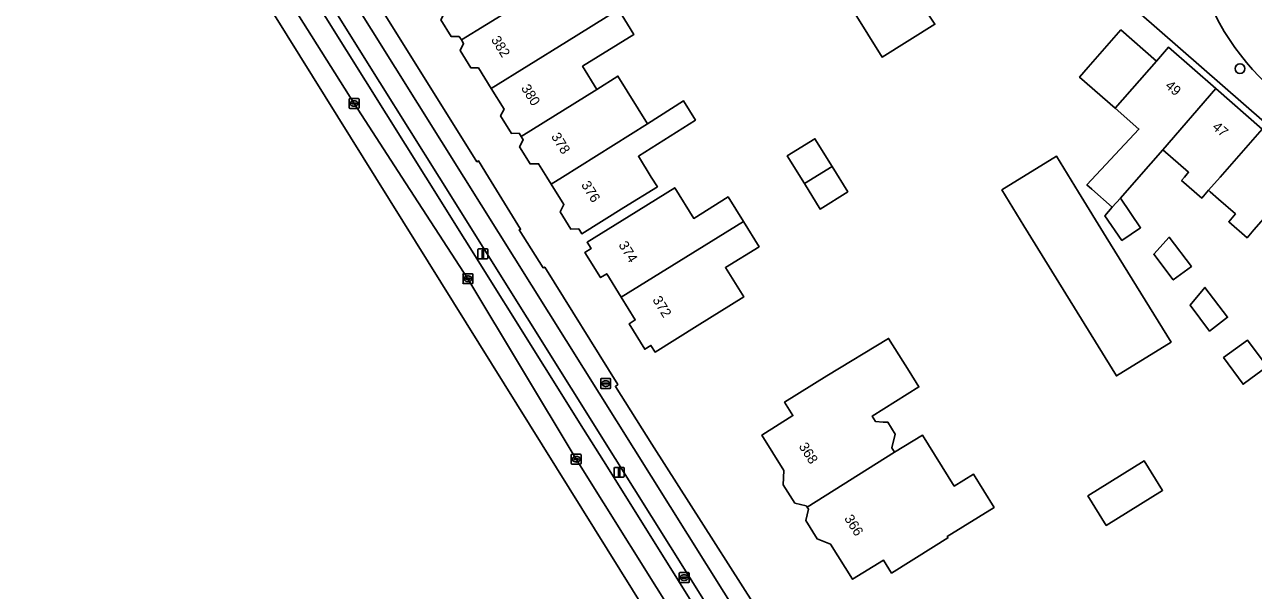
# Model space of a CAD drawing. Extents: x 160023 to 161302, y 384750 to 385707.
# Drawn here: x 160026 to 160150, y 385208.4 to 385265.4 of the extents above; entities that cross this region are included whole.
import ezdxf

# ---------------------------------------------------------------- set-up
doc = ezdxf.new("R2010")
doc.units = 0
for name, color, linetype in [('IMGEO_Berm_open', 7, 'Continuous'), ('IMGEO_Boom', 7, 'Continuous'), ('IMGEO_Brandkraan', 7, 'Continuous'), ('IMGEO_Erf', 7, 'Continuous'), ('IMGEO_Fietspad_gesloten', 7, 'Continuous'), ('IMGEO_Kolk', 7, 'Continuous'), ('IMGEO_Lichtmast', 7, 'Continuous'), ('IMGEO_Pand', 7, 'Continuous'), ('IMGEO_Pand_nummerreeks', 7, 'Continuous'), ('IMGEO_Parkeervlak_open', 7, 'Continuous'), ('IMGEO_Rijbaan_lokaal_gesloten', 7, 'Continuous'), ('IMGEO_Rijbaan_regionaal_gesloten', 7, 'Continuous'), ('IMGEO_Rioolput', 7, 'Continuous'), ('IMGEO_Voetpad_open', 7, 'Continuous')]:
    doc.layers.add(name, color=color, linetype=linetype)

msp = doc.modelspace()

# ---------------------------------------------------------------- linework, layer by layer
at = {"layer": 'IMGEO_Berm_open'}
for points in [[(160150.57, 385117.95), (160124.15, 385160.16), (160085.58, 385221.63), (160067.83, 385250), (160061.87, 385259.54), (160032.54, 385306.42)], [(160040.41, 385291.63), (160066.49, 385250), (160082.4, 385224.6), (160084.81, 385220.76), (160099.16, 385197.85), (160101.17, 385194.65), (160111.68, 385177.87), (160112.14, 385178.14), (160114.11, 385174.95), (160113.69, 385174.67), (160123.81, 385158.57), (160123.88, 385157.79), (160123.49, 385155.85)]]:
    msp.add_lwpolyline(points, dxfattribs=at)
at = {"layer": 'IMGEO_Boom'}
msp.add_circle((160148.61, 385260.93), 0.489, dxfattribs=at)
at = {"layer": 'IMGEO_Brandkraan'}
for p, q in [((160084.14, 385228.76), (160084.14, 385229.62)), ((160084.22, 385229.69), (160085.07, 385229.69)), ((160084.4, 385229.18), (160084.4, 385229.2)), ((160084.44, 385229.23), (160084.84, 385229.23)), ((160084.84, 385229.15), (160084.44, 385229.15)), ((160084.63, 385229.47), (160084.66, 385229.47)), ((160084.89, 385229.2), (160084.89, 385229.18)), ((160085.14, 385229.62), (160085.14, 385228.76)), ((160085.07, 385228.69), (160084.22, 385228.69)), ((160084.65, 385228.91), (160084.63, 385228.91))]:
    msp.add_line(p, q, dxfattribs=at)
for points in [[(160084.14, 385228.76), (160084.14, 385229.62)], [(160084.22, 385229.69), (160085.07, 385229.69)], [(160085.14, 385229.62), (160085.14, 385228.76)], [(160085.07, 385228.69), (160084.22, 385228.69)]]:
    msp.add_lwpolyline(points, dxfattribs=at)
for centre, radius, start, end in [((160084.22, 385229.62), 0.0765, 91.552, 178.448), ((160084.22, 385229.62), 0.0765, 91.552, 178.448), ((160084.44, 385229.19), 0.0403, 85.8775, 175.7526), ((160084.44, 385229.18), 0.0366, 178.938, 274.7102), ((160084.85, 385229.2), 0.0386, 1.7309, 96.639), ((160084.84, 385229.19), 0.043, 264.8664, 352.4533), ((160085.07, 385229.62), 0.0765, 1.552, 88.448), ((160085.07, 385229.62), 0.0765, 1.552, 88.448), ((160084.22, 385228.77), 0.0765, 181.552, 268.448), ((160084.22, 385228.77), 0.0765, 181.552, 268.448), ((160085.07, 385228.77), 0.0765, 271.552, 358.448), ((160085.07, 385228.77), 0.0765, 271.552, 358.448)]:
    msp.add_arc(centre, radius, start, end, dxfattribs=at)
for centre, major_axis, ratio, start_param, end_param in [((160084.63, 385229.19), (-0.387, 0.002), 0.722429, 4.712389, 7.853982), ((160084.65, 385229.19), (-0.39, 0.002), 0.717154, 1.570796, 4.712389)]:
    msp.add_ellipse(centre, major_axis=major_axis, ratio=ratio, start_param=start_param, end_param=end_param, dxfattribs=at)
at = {"layer": 'IMGEO_Erf'}
for points in [[(160152.01, 385315.35), (160133.21, 385328.22), (160132.92, 385328.42), (160128.79, 385322.11), (160120.91, 385304.2), (160118.51, 385298.76), (160117.26, 385295.93), (160116.02, 385293.09), (160114.77, 385290.25), (160113.7, 385287.74), (160114.62, 385287.35), (160116.68, 385286.45), (160114.75, 385282.01), (160113.13, 385278.26), (160115.09, 385275.32), (160112.42, 385273.54), (160114.46, 385270.47), (160117.84, 385265.4), (160112.51, 385262.09), (160109.63, 385266.73), (160106.44, 385271.87)], [(160050.76, 385284.96), (160071.65, 385251.54), (160071.81, 385251.64), (160072.82, 385250), (160076.05, 385244.74), (160075.93, 385244.69), (160078.33, 385240.86), (160078.49, 385240.93), (160085.88, 385229.1), (160085.62, 385228.91), (160089.29, 385223.09), (160103.46, 385200.92)], [(160157.45, 385250), (160136.27, 385268.49)], [(160085.93, 385266.87), (160087.48, 385264.38), (160082.31, 385261.17), (160083.75, 385258.84), (160085.88, 385260.17), (160088.85, 385255.37), (160092.49, 385257.68), (160093.69, 385255.75), (160087.94, 385252.09), (160089.24, 385250), (160089.85, 385249.02), (160086.48, 385246.92), (160082.23, 385244.29), (160081.93, 385244.77), (160081.14, 385244.75), (160080.05, 385246.51), (160080.43, 385247.22), (160079.14, 385249.28), (160078.7, 385250), (160077.87, 385251.34), (160077.02, 385251.32), (160075.95, 385253.05), (160076.33, 385253.75), (160076.11, 385254.09), (160075.9, 385254.42), (160075.14, 385254.4), (160074.04, 385256.17), (160074.4, 385256.85), (160073.1, 385258.94), (160071.81, 385261.02), (160071.04, 385261), (160069.95, 385262.77), (160070.31, 385263.46), (160070.09, 385263.82), (160069.86, 385264.18), (160069.06, 385264.15), (160068.01, 385265.85)], [(160150.02, 385244.67), (160149.33, 385243.88), (160147.48, 385245.5), (160148.16, 385246.29), (160146.44, 385247.79), (160145.61, 385248.52), (160145.44, 385248.67), (160144.76, 385247.89), (160142.72, 385249.67), (160143.01, 385250), (160143.43, 385250.48), (160140.82, 385252.76), (160138.4, 385250), (160136.55, 385247.88), (160138.59, 385244.9), (160136.7, 385243.61), (160134.99, 385246.1), (160135.74, 385246.96), (160133.67, 385248.78), (160133.18, 385249.21), (160138.42, 385254.83), (160136.02, 385256.93), (160132.44, 385260.06), (160133.31, 385261.06), (160136.6, 385264.82), (160140.18, 385261.69), (160141.41, 385263.09), (160146.19, 385258.91), (160150.84, 385254.84)]]:
    msp.add_lwpolyline(points, dxfattribs=at)
for points in [[(160109.06, 385248.52), (160106.26, 385246.78), (160104.68, 385249.34), (160102.95, 385252.13), (160105.75, 385253.87), (160107.48, 385251.07)], [(160130.12, 385252.09), (160132.34, 385248.49), (160135.13, 385243.96), (160141.66, 385233.37), (160136.16, 385229.97), (160126.83, 385245.1), (160124.61, 385248.7)], [(160100.11, 385242.98), (160096.72, 385240.88), (160098.56, 385237.92), (160093.87, 385235.01), (160089.62, 385232.37), (160089.2, 385233.04), (160088.58, 385232.65), (160087, 385235.21), (160087.63, 385235.6), (160086.2, 385237.9), (160084.74, 385240.26), (160084.12, 385239.88), (160082.55, 385242.41), (160083.17, 385242.8), (160082.77, 385243.44), (160087.02, 385246.07), (160091.61, 385248.92), (160093.52, 385245.84), (160096.99, 385248), (160098.53, 385245.53)], [(160141.48, 385243.94), (160143.71, 385241), (160141.89, 385239.63), (160139.92, 385242.22)], [(160145.08, 385238.88), (160147.36, 385235.87), (160145.55, 385234.49), (160143.58, 385237.09)], [(160121.73, 385220.08), (160123.82, 385216.71), (160119.09, 385213.77), (160119.16, 385213.64), (160117.71, 385212.74), (160113.47, 385210.1), (160112.66, 385211.4), (160109.55, 385209.47), (160107.33, 385213), (160105.96, 385213.55), (160104.82, 385215.38), (160105.08, 385216.53), (160104.96, 385216.73), (160104.86, 385216.89), (160103.73, 385217.15), (160102.55, 385218.98), (160102.62, 385220.43), (160100.39, 385224), (160103.53, 385225.96), (160102.68, 385227.33), (160106.93, 385229.97), (160113.18, 385233.75), (160115.24, 385230.44), (160116.23, 385228.86), (160111.52, 385225.92), (160111.86, 385225.37), (160112.62, 385225.32), (160113.1, 385225.3), (160113.85, 385224.09), (160113.5, 385222.73), (160113.78, 385222.29), (160116.59, 385224.01), (160119.79, 385218.87)], [(160149.37, 385233.58), (160151.34, 385230.9), (160149.07, 385229.23), (160148.93, 385229.13), (160146.96, 385231.81)], [(160138.95, 385221.42), (160140.81, 385218.43), (160135.13, 385214.9), (160133.27, 385217.88)]]:
    msp.add_lwpolyline(points, close=True, dxfattribs=at)
at = {"layer": 'IMGEO_Fietspad_gesloten'}
msp.add_lwpolyline([(160026.03, 385317.31), (160026.04, 385317.29), (160028.01, 385313.74), (160028.32, 385313.16), (160030.44, 385309.78), (160032.54, 385306.42), (160061.87, 385259.54), (160067.83, 385250), (160085.58, 385221.63), (160124.15, 385160.16), (160150.57, 385117.95), (160168.15, 385089.8), (160170.06, 385090.86), (160169.92, 385091.09), (160127.68, 385158.49), (160123.78, 385164.74), (160087.49, 385222.64), (160070.35, 385250), (160030.7, 385313.28), (160030.2, 385314.14), (160029.34, 385315.62), (160028.12, 385317.71), (160027.3, 385319.1), (160027.28, 385319.14)], close=True, dxfattribs=at)
at = {"layer": 'IMGEO_Kolk'}
for p, q in [((160058.76, 385256.99), (160058.76, 385257.84)), ((160058.84, 385257.91), (160059.69, 385257.91)), ((160059.25, 385257.69), (160059.28, 385257.69)), ((160059.77, 385257.84), (160059.77, 385256.99)), ((160059.69, 385256.91), (160058.84, 385256.91)), ((160059.02, 385257.41), (160059.02, 385257.42)), ((160059.46, 385257.37), (160059.06, 385257.37)), ((160059.07, 385257.46), (160059.46, 385257.46)), ((160059.27, 385257.13), (160059.25, 385257.13)), ((160059.51, 385257.42), (160059.51, 385257.41)), ((160070.25, 385239.33), (160070.25, 385240.19)), ((160070.32, 385240.26), (160071.18, 385240.26)), ((160071.25, 385240.19), (160071.25, 385239.33)), ((160071.18, 385239.26), (160070.32, 385239.26)), ((160070.51, 385239.75), (160070.51, 385239.77)), ((160070.55, 385239.8), (160070.95, 385239.8)), ((160070.94, 385239.72), (160070.55, 385239.72)), ((160070.76, 385239.48), (160070.73, 385239.48)), ((160070.74, 385240.04), (160070.76, 385240.04)), ((160070.99, 385239.77), (160070.99, 385239.75)), ((160081.17, 385221.15), (160081.17, 385222)), ((160081.24, 385222.07), (160082.09, 385222.07)), ((160081.42, 385221.57), (160081.42, 385221.58)), ((160081.47, 385221.62), (160081.87, 385221.62)), ((160081.65, 385221.85), (160081.68, 385221.85)), ((160081.91, 385221.58), (160081.91, 385221.57)), ((160082.17, 385222), (160082.17, 385221.15)), ((160082.09, 385221.07), (160081.24, 385221.07)), ((160081.86, 385221.53), (160081.46, 385221.53)), ((160081.68, 385221.29), (160081.65, 385221.29))]:
    msp.add_line(p, q, dxfattribs=at)
for points in [[(160058.76, 385256.99), (160058.76, 385257.84)], [(160058.84, 385257.91), (160059.69, 385257.91)], [(160059.77, 385257.84), (160059.77, 385256.99)], [(160059.69, 385256.91), (160058.84, 385256.91)], [(160070.25, 385239.33), (160070.25, 385240.19)], [(160070.32, 385240.26), (160071.18, 385240.26)], [(160071.25, 385240.19), (160071.25, 385239.33)], [(160071.18, 385239.26), (160070.32, 385239.26)], [(160081.17, 385221.15), (160081.17, 385222)], [(160081.24, 385222.07), (160082.09, 385222.07)], [(160082.17, 385222), (160082.17, 385221.15)], [(160082.09, 385221.07), (160081.24, 385221.07)]]:
    msp.add_lwpolyline(points, dxfattribs=at)
for centre, radius, start, end in [((160058.84, 385257.84), 0.0765, 91.552, 178.448), ((160058.84, 385257.84), 0.0765, 91.552, 178.448), ((160059.69, 385257.84), 0.0765, 1.552, 88.448), ((160059.69, 385257.84), 0.0765, 1.552, 88.448), ((160058.84, 385256.99), 0.0765, 181.552, 268.448), ((160058.84, 385256.99), 0.0765, 181.552, 268.448), ((160059.06, 385257.42), 0.0403, 85.8775, 175.7526), ((160059.06, 385257.41), 0.0366, 178.938, 274.7102), ((160059.47, 385257.42), 0.0386, 1.7309, 96.639), ((160059.46, 385257.41), 0.043, 264.8664, 352.4533), ((160059.69, 385256.99), 0.0765, 271.552, 358.448), ((160059.69, 385256.99), 0.0765, 271.552, 358.448), ((160070.32, 385240.19), 0.0765, 91.552, 178.448), ((160070.32, 385240.19), 0.0765, 91.552, 178.448), ((160071.17, 385240.19), 0.0765, 1.552, 88.448), ((160071.17, 385240.19), 0.0765, 1.552, 88.448), ((160070.32, 385239.34), 0.0765, 181.552, 268.448), ((160070.32, 385239.34), 0.0765, 181.552, 268.448), ((160070.55, 385239.76), 0.0403, 85.8775, 175.7526), ((160070.54, 385239.75), 0.0366, 178.938, 274.7102), ((160070.95, 385239.76), 0.043, 264.8664, 352.4533), ((160070.95, 385239.77), 0.0386, 1.7309, 96.639), ((160071.17, 385239.34), 0.0765, 271.552, 358.448), ((160071.17, 385239.34), 0.0765, 271.552, 358.448), ((160081.24, 385222), 0.0765, 91.552, 178.448), ((160081.24, 385222), 0.0765, 91.552, 178.448), ((160081.47, 385221.58), 0.0403, 85.8775, 175.7526), ((160081.46, 385221.57), 0.0366, 178.938, 274.7102), ((160081.87, 385221.57), 0.043, 264.8664, 352.4533), ((160081.87, 385221.58), 0.0386, 1.7309, 96.639), ((160082.09, 385222), 0.0765, 1.552, 88.448), ((160082.09, 385222), 0.0765, 1.552, 88.448), ((160081.24, 385221.15), 0.0765, 181.552, 268.448), ((160081.24, 385221.15), 0.0765, 181.552, 268.448), ((160082.09, 385221.15), 0.0765, 271.552, 358.448), ((160082.09, 385221.15), 0.0765, 271.552, 358.448)]:
    msp.add_arc(centre, radius, start, end, dxfattribs=at)
for centre, major_axis, ratio, start_param, end_param in [((160059.25, 385257.41), (-0.387, 0.002), 0.722429, 4.712389, 7.853982), ((160059.28, 385257.41), (-0.39, 0.002), 0.717154, 1.570796, 4.712389), ((160070.74, 385239.76), (-0.387, 0.002), 0.722429, 4.712389, 7.853982), ((160070.76, 385239.76), (-0.39, 0.002), 0.717154, 1.570796, 4.712389), ((160081.65, 385221.57), (-0.387, 0.002), 0.722429, 4.712389, 7.853982), ((160081.68, 385221.57), (-0.39, 0.002), 0.717154, 1.570796, 4.712389)]:
    msp.add_ellipse(centre, major_axis=major_axis, ratio=ratio, start_param=start_param, end_param=end_param, dxfattribs=at)
at = {"layer": 'IMGEO_Lichtmast'}
for p, q in [((160071.76, 385241.86), (160071.76, 385242.66)), ((160071.76, 385242.66), (160071.76, 385241.86)), ((160071.86, 385242.76), (160072.65, 385242.76)), ((160072.65, 385242.76), (160071.86, 385242.76)), ((160072.75, 385242.66), (160072.75, 385241.86)), ((160072.75, 385241.86), (160072.75, 385242.66)), ((160072.65, 385241.76), (160071.86, 385241.76)), ((160071.86, 385241.76), (160072.65, 385241.76)), ((160085.51, 385219.85), (160085.51, 385220.65)), ((160085.51, 385220.65), (160085.51, 385219.85)), ((160085.61, 385220.75), (160086.4, 385220.75)), ((160086.4, 385220.75), (160085.61, 385220.75)), ((160086.5, 385220.65), (160086.5, 385219.85)), ((160086.5, 385219.85), (160086.5, 385220.65)), ((160086.4, 385219.75), (160085.61, 385219.75)), ((160085.61, 385219.75), (160086.4, 385219.75))]:
    msp.add_line(p, q, dxfattribs=at)
for points in [[(160072.18, 385242.63), (160072.33, 385242.63), (160072.33, 385241.88), (160072.18, 385241.88), (160072.18, 385242.63)], [(160085.93, 385220.63), (160086.08, 385220.63), (160086.08, 385219.88), (160085.93, 385219.88), (160085.93, 385220.63)]]:
    msp.add_lwpolyline(points, dxfattribs=at)
for centre, start, end in [((160071.86, 385242.66), 90, 180), ((160071.86, 385242.66), 90, 180), ((160072.65, 385242.66), 0, 90), ((160072.65, 385242.66), 360, 90), ((160071.86, 385241.86), 180, 270), ((160071.86, 385241.86), 180, 270), ((160072.65, 385241.86), 270, 0), ((160072.65, 385241.86), 270, 0), ((160085.61, 385220.65), 90, 180), ((160085.61, 385220.65), 90, 180), ((160086.4, 385220.65), 0, 90), ((160086.4, 385220.65), 360, 90), ((160085.61, 385219.85), 180, 270), ((160085.61, 385219.85), 180, 270), ((160086.4, 385219.85), 270, 0), ((160086.4, 385219.85), 270, 0)]:
    msp.add_arc(centre, 0.1, start, end, dxfattribs=at)
at = {"layer": 'IMGEO_Pand'}
for points in [[(160075.76, 385271.56), (160080.95, 385274.78), (160079.85, 385276.55), (160077.21, 385274.91), (160074.67, 385273.34), (160067.09, 385268.63), (160068.38, 385266.55), (160068.01, 385265.85), (160069.06, 385264.15), (160069.86, 385264.18), (160070.09, 385263.82), (160077.66, 385268.49)], [(160085.93, 385266.87), (160089.36, 385268.98), (160089.78, 385269.24), (160089.58, 385269.57), (160088.45, 385271.38), (160085.79, 385270.61), (160082.46, 385268.57), (160081.17, 385270.66), (160080.77, 385270.41), (160077.66, 385268.49), (160070.09, 385263.82), (160070.31, 385263.46), (160069.95, 385262.77), (160071.04, 385261), (160071.81, 385261.02), (160073.1, 385258.94), (160080.68, 385263.64)], [(160114.46, 385270.47), (160112.05, 385268.87), (160111.51, 385269.68), (160111.41, 385269.61), (160111.51, 385269.45), (160111.22, 385269.26), (160111.91, 385268.18), (160109.63, 385266.73), (160112.51, 385262.09), (160117.84, 385265.4)], [(160082.31, 385261.17), (160087.48, 385264.38), (160085.93, 385266.87), (160080.68, 385263.64), (160073.1, 385258.94), (160074.4, 385256.85), (160074.04, 385256.17), (160075.14, 385254.4), (160075.9, 385254.42), (160076.11, 385254.09), (160083.75, 385258.84)], [(160132.44, 385260.06), (160136.02, 385256.93), (160140.18, 385261.69), (160136.6, 385264.82), (160133.31, 385261.06)], [(160146.19, 385258.91), (160141.41, 385263.09), (160140.18, 385261.69), (160136.02, 385256.93), (160138.42, 385254.83), (160133.18, 385249.21), (160133.67, 385248.78), (160135.74, 385246.96), (160136.55, 385247.88), (160138.4, 385250), (160140.82, 385252.76)], [(160085.88, 385260.17), (160083.75, 385258.84), (160076.11, 385254.09), (160076.33, 385253.75), (160075.95, 385253.05), (160077.02, 385251.32), (160077.87, 385251.34), (160078.7, 385250), (160079.14, 385249.28), (160080.3, 385250), (160088.85, 385255.37)], [(160150.84, 385254.84), (160146.19, 385258.91), (160140.82, 385252.76), (160143.43, 385250.48), (160143.01, 385250), (160142.72, 385249.67), (160144.76, 385247.89), (160145.44, 385248.67), (160146.61, 385250)], [(160093.69, 385255.75), (160092.49, 385257.68), (160088.85, 385255.37), (160080.3, 385250), (160079.14, 385249.28), (160080.43, 385247.22), (160080.05, 385246.51), (160081.14, 385244.75), (160081.93, 385244.77), (160082.23, 385244.29), (160086.48, 385246.92), (160089.85, 385249.02), (160089.24, 385250), (160087.94, 385252.09)], [(160104.68, 385249.34), (160107.48, 385251.07), (160105.75, 385253.87), (160102.95, 385252.13)], [(160155.42, 385250.84), (160150.84, 385254.84), (160146.61, 385250), (160145.44, 385248.67), (160145.61, 385248.52), (160146.44, 385247.79), (160148.16, 385246.29), (160147.48, 385245.5), (160149.33, 385243.88), (160150.02, 385244.67), (160154.68, 385250)], [(160132.34, 385248.49), (160130.12, 385252.09), (160124.61, 385248.7), (160126.83, 385245.1), (160136.16, 385229.97), (160141.66, 385233.37), (160135.13, 385243.96)], [(160107.48, 385251.07), (160104.68, 385249.34), (160106.26, 385246.78), (160109.06, 385248.52)], [(160086.2, 385237.9), (160098.53, 385245.53), (160096.99, 385248), (160093.52, 385245.84), (160091.61, 385248.92), (160087.02, 385246.07), (160082.77, 385243.44), (160083.17, 385242.8), (160082.55, 385242.41), (160084.12, 385239.88), (160084.74, 385240.26)], [(160136.55, 385247.88), (160135.74, 385246.96), (160134.99, 385246.1), (160136.7, 385243.61), (160138.59, 385244.9)], [(160093.87, 385235.01), (160098.56, 385237.92), (160096.72, 385240.88), (160100.11, 385242.98), (160098.53, 385245.53), (160086.2, 385237.9), (160087.63, 385235.6), (160087, 385235.21), (160088.58, 385232.65), (160089.2, 385233.04), (160089.62, 385232.37)], [(160139.92, 385242.22), (160141.89, 385239.63), (160143.71, 385241), (160141.48, 385243.94)], [(160143.58, 385237.09), (160145.55, 385234.49), (160147.36, 385235.87), (160145.08, 385238.88)], [(160111.52, 385225.92), (160116.23, 385228.86), (160115.24, 385230.44), (160113.18, 385233.75), (160106.93, 385229.97), (160102.68, 385227.33), (160103.53, 385225.96), (160100.39, 385224), (160102.62, 385220.43), (160102.55, 385218.98), (160103.73, 385217.15), (160104.86, 385216.89), (160104.96, 385216.73), (160113.78, 385222.29), (160113.5, 385222.73), (160113.85, 385224.09), (160113.1, 385225.3), (160112.62, 385225.32), (160111.86, 385225.37)], [(160149.07, 385229.23), (160151.34, 385230.9), (160149.37, 385233.58), (160146.96, 385231.81), (160148.93, 385229.13)], [(160117.71, 385212.74), (160119.16, 385213.64), (160119.09, 385213.77), (160123.82, 385216.71), (160121.73, 385220.08), (160119.79, 385218.87), (160116.59, 385224.01), (160113.78, 385222.29), (160104.96, 385216.73), (160105.08, 385216.53), (160104.82, 385215.38), (160105.96, 385213.55), (160107.33, 385213), (160109.55, 385209.47), (160112.66, 385211.4), (160113.47, 385210.1)], [(160133.27, 385217.88), (160135.13, 385214.9), (160140.81, 385218.43), (160138.95, 385221.42)]]:
    msp.add_lwpolyline(points, close=True, dxfattribs=at)
at = {"layer": 'IMGEO_Parkeervlak_open'}
for points in [[(160036.65, 385293.45), (160037.98, 385291.32), (160044.01, 385281.7), (160048.49, 385274.56), (160059.26, 385257.41), (160064.09, 385250), (160070.75, 385239.76), (160081.67, 385221.57), (160092.51, 385204.26), (160103.41, 385186.88), (160114.43, 385169.25), (160123.75, 385154.33)], [(160123.49, 385155.85), (160123.88, 385157.79), (160123.81, 385158.57), (160113.69, 385174.67), (160111.68, 385177.87), (160101.17, 385194.65), (160099.16, 385197.85), (160084.81, 385220.76), (160082.4, 385224.6), (160066.49, 385250), (160040.41, 385291.63)]]:
    msp.add_lwpolyline(points, dxfattribs=at)
at = {"layer": 'IMGEO_Rijbaan_lokaal_gesloten'}
msp.add_arc((160168.73, 385277.84), 25.38, 191.7936, 226.4224, dxfattribs=at)
at = {"layer": 'IMGEO_Rijbaan_regionaal_gesloten'}
msp.add_lwpolyline([(160147.22, 385116.92), (160136.55, 385133.95), (160126.75, 385149.48), (160126.19, 385150.49), (160123.75, 385154.33), (160114.43, 385169.25), (160103.41, 385186.88), (160092.51, 385204.26), (160081.67, 385221.57), (160070.75, 385239.76), (160064.09, 385250), (160059.26, 385257.41), (160048.49, 385274.56), (160044.01, 385281.7), (160037.98, 385291.32), (160036.65, 385293.45), (160033.75, 385294.44), (160038.31, 385287.12), (160087.33, 385208.4), (160132.35, 385136.18), (160151.88, 385106.94)], dxfattribs=at)
at = {"layer": 'IMGEO_Rioolput'}
for p, q in [((160092.06, 385209.21), (160092.06, 385210.06)), ((160092.13, 385210.14), (160092.98, 385210.14)), ((160092.32, 385209.63), (160092.32, 385209.64)), ((160092.36, 385209.68), (160092.76, 385209.68)), ((160092.75, 385209.59), (160092.36, 385209.59)), ((160092.57, 385209.36), (160092.54, 385209.36)), ((160092.55, 385209.92), (160092.57, 385209.92)), ((160092.8, 385209.64), (160092.8, 385209.63)), ((160093.06, 385210.06), (160093.06, 385209.21)), ((160092.98, 385209.14), (160092.13, 385209.14))]:
    msp.add_line(p, q, dxfattribs=at)
for points in [[(160092.06, 385209.21), (160092.06, 385210.06)], [(160092.13, 385210.14), (160092.98, 385210.14)], [(160093.06, 385210.06), (160093.06, 385209.21)], [(160092.98, 385209.14), (160092.13, 385209.14)]]:
    msp.add_lwpolyline(points, dxfattribs=at)
for centre, radius, start, end in [((160092.13, 385210.06), 0.0765, 91.552, 178.448), ((160092.13, 385210.06), 0.0765, 91.552, 178.448), ((160092.13, 385209.21), 0.0765, 181.552, 268.448), ((160092.13, 385209.21), 0.0765, 181.552, 268.448), ((160092.36, 385209.64), 0.0403, 85.8775, 175.7526), ((160092.35, 385209.63), 0.0366, 178.938, 274.7102), ((160092.76, 385209.64), 0.043, 264.8664, 352.4533), ((160092.76, 385209.64), 0.0386, 1.7309, 96.639), ((160092.98, 385210.06), 0.0765, 1.552, 88.448), ((160092.98, 385210.06), 0.0765, 1.552, 88.448), ((160092.98, 385209.21), 0.0765, 271.552, 358.448), ((160092.98, 385209.21), 0.0765, 271.552, 358.448)]:
    msp.add_arc(centre, radius, start, end, dxfattribs=at)
for centre, major_axis, ratio, start_param, end_param in [((160092.54, 385209.64), (-0.387, 0.002), 0.722429, 4.712389, 7.853982), ((160092.57, 385209.64), (-0.39, 0.002), 0.717154, 1.570796, 4.712389)]:
    msp.add_ellipse(centre, major_axis=major_axis, ratio=ratio, start_param=start_param, end_param=end_param, dxfattribs=at)
at = {"layer": 'IMGEO_Voetpad_open'}
for points in [[(160103.46, 385200.92), (160089.29, 385223.09), (160085.62, 385228.91), (160085.88, 385229.1), (160078.49, 385240.93), (160078.33, 385240.86), (160075.93, 385244.69), (160076.05, 385244.74), (160072.82, 385250), (160071.81, 385251.64), (160071.65, 385251.54), (160050.76, 385284.96), (160050.29, 385285.71), (160046.58, 385291.66), (160040.82, 385300.82), (160040.99, 385300.92), (160037.94, 385305.85), (160038.15, 385305.98), (160032.62, 385314.91)], [(160030.2, 385314.14), (160030.7, 385313.28), (160070.35, 385250), (160087.49, 385222.64), (160123.78, 385164.74)], [(160136.27, 385268.49), (160157.45, 385250), (160189.22, 385222.22), (160189.9, 385221.61), (160192.37, 385219.55), (160193, 385220.27), (160193.42, 385220.74), (160193.02, 385221.09), (160193.21, 385221.32), (160193, 385221.5), (160193.71, 385222.29), (160191.37, 385224.41), (160173.33, 385240.2)]]:
    msp.add_lwpolyline(points, dxfattribs=at)
msp.add_arc((160168.73, 385277.84), 25.38, 191.7936, 226.4224, dxfattribs=at)

# ---------------------------------------------------------------- texts
at = {"layer": 'IMGEO_Pand_nummerreeks'}
for s, rotation, p in [('382', 301.862, (160073.04, 385263.85)), ('380', 301.862, (160076.07, 385258.97)), ('49', 318.8273, (160141, 385259.09)), ('47', 318.8273, (160145.75, 385254.93)), ('378', 301.8648, (160079.1, 385254.1)), ('376', 301.8648, (160082.13, 385249.23)), ('374', 301.7347, (160085.9, 385243.17)), ('372', 301.7347, (160089.32, 385237.64)), ('368', 302.2401, (160104.08, 385222.87)), ('366', 302.238, (160108.66, 385215.61))]:
    msp.add_text(s, height=1, rotation=rotation, dxfattribs=at).set_placement(p)

doc.saveas('drawing.dxf')
